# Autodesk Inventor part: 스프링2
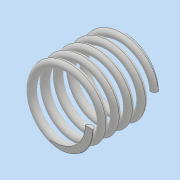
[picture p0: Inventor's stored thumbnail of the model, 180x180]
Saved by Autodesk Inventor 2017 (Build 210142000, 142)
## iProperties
Part Number: 스프링2
Material: 일반
Document SubType Name: Modeling
Designer: MRC
Density: 1 g/cm^3
Appearance: 기본값
Mass: 0.819704 g
Surface Area: 16.7052 cm^2
Volume: 0.819704 cm^3
Author: MRC
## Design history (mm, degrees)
sketch "스케치1"
  geometry: L1 (0, 0)-(0, 17.5); L2 (0, 0)-(8.5, 0); L3 (0, 17.5)-(8.5, 17.5); C1 r 1 at (8.5, 0)
  constraints: 6 end point, 2 horizontal, 1 centre point, 1 coincident, 1 parallel, 1 vertical
  dimensions: "d0" = 17.5 distance of L1.start L1.end (derived); "d1" = 17 diameter of L2.end L1; "d2" = 2 diameter of C1
feature "코일1" sketch "스케치1" pitch "d3" = 10; turns "d5" = 5; dims "d4" = 17.5 (= d0), "d6" = 0, angle "d7" = 90 deg, angle "d8" = 90 deg, "d9" = 0, "d10" = 0
sketch "스케치2"
  geometry: L1 (17.5, 14.331)-(0, 14.331); L2 (0, 14.331)-(0, -14.331); L3 (0, -14.331)-(17.5, -14.331); L4 (17.5, -14.331)-(17.5, 14.331); 2 further points
  constraints: 8 end point, 2 parallel, 1 coincident, 1 horizontal, 1 midpoint, 1 perpendicular
  dimensions: "d11" = 28.66142 distance of L3.end L1.start; "d12" = 17.5 distance of L2.end L3.end (= d0)
extrude "돌출1" sketch "스케치2" stored distance "d13" = 0; taper "d14" = 0 deg
node "솔리드1"
